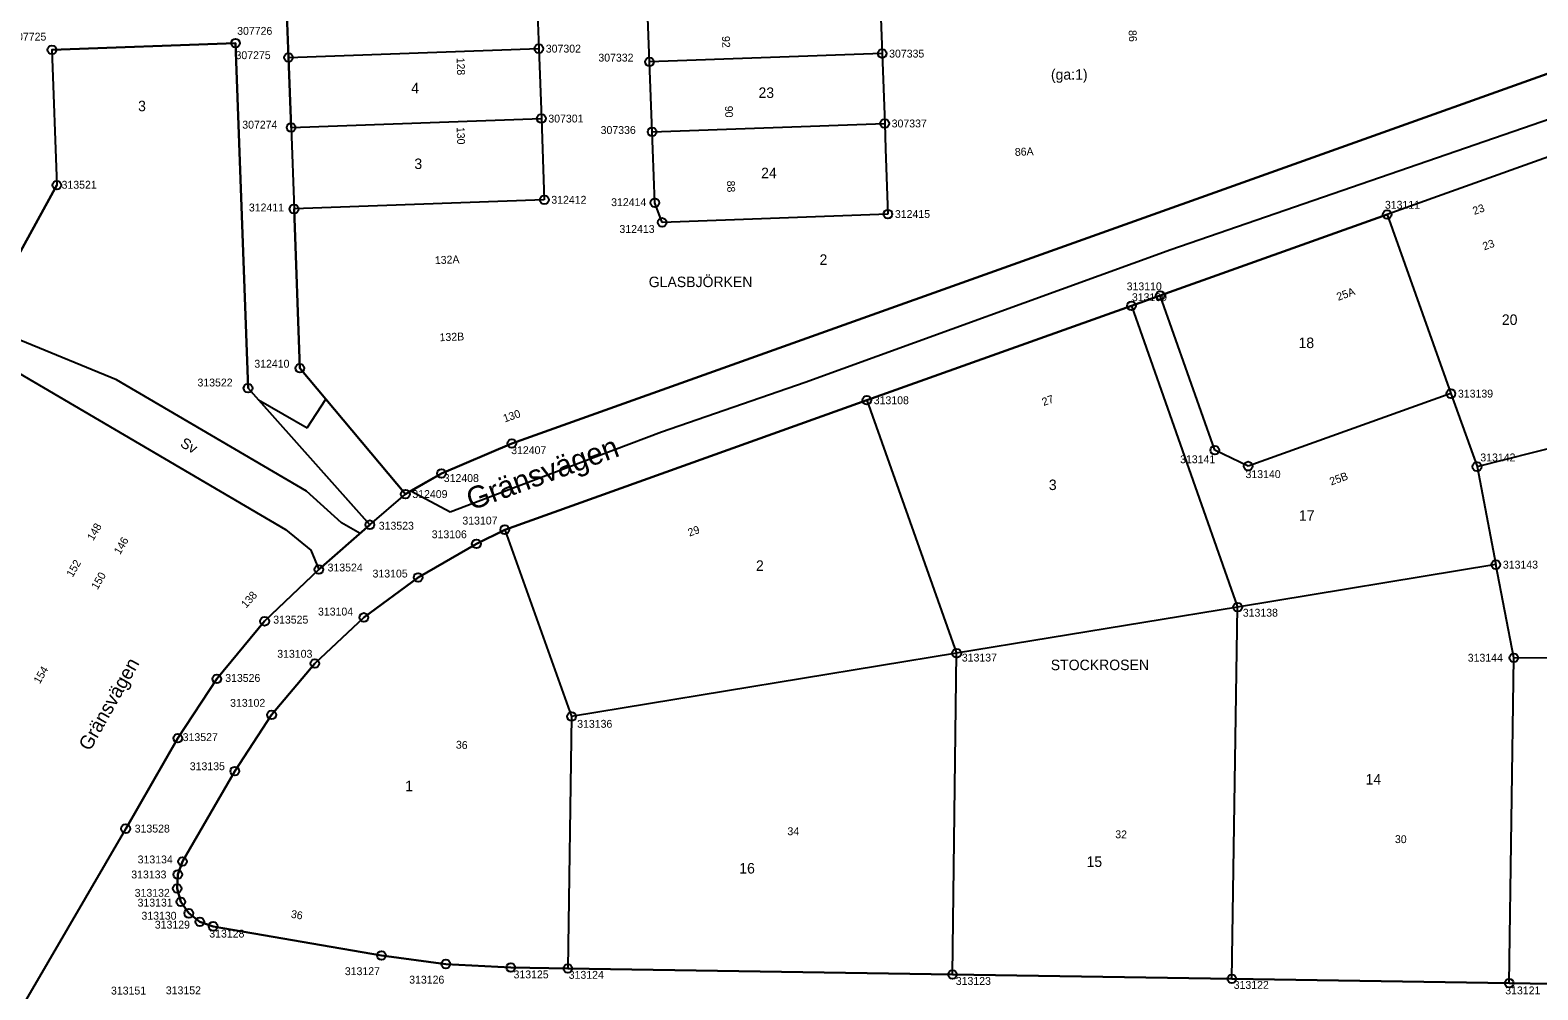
# Model space of a CAD drawing. Extents: x 141995 to 152570, y 6580184 to 6586000.
# Drawn here: x 142575.6 to 142748, y 6585148.7 to 6585258.5 of the extents above; entities that cross this region are included whole.
import ezdxf

# ---------------------------------------------------------------- set-up
doc = ezdxf.new("R2010")
doc.units = 0
for name, color, linetype in [('Level 10', 7, 'Continuous'), ('Level 13', 7, 'Continuous'), ('Level 33', 7, 'Continuous'), ('Level 41', 7, 'Continuous'), ('Level 43', 7, 'Continuous'), ('Level 48', 7, 'Continuous'), ('Level 5', 7, 'Continuous'), ('Level 50', 7, 'Continuous'), ('Level 51', 7, 'Continuous'), ('Level 53', 7, 'Continuous'), ('Level 54', 7, 'Continuous'), ('Level 55', 7, 'Continuous'), ('Level 58', 7, 'Continuous'), ('Level 59', 7, 'Continuous'), ('Level 6', 7, 'Continuous'), ('Level 7', 7, 'Continuous')]:
    doc.layers.add(name, color=color, linetype=linetype)

msp = doc.modelspace()

# ---------------------------------------------------------------- linework, layer by layer
at = {"layer": 'Level 10'}
for centre in [(142578.05, 6585256.21), (142599.03, 6585256.98), (142633.72, 6585256.34), (142605.1, 6585255.32), (142646.37, 6585254.82), (142672.98, 6585255.77), (142634.01, 6585248.34), (142673.27, 6585247.78), (142605.39, 6585247.32), (142646.67, 6585246.83), (142578.61, 6585240.72), (142634.35, 6585239.05), (142605.73, 6585238), (142646.98, 6585238.72), (142673.64, 6585237.42), (142730.72, 6585237.37), (142647.82, 6585236.47), (142701.48, 6585226.92), (142704.78, 6585228.1), (142606.4, 6585219.78), (142600.47, 6585217.5), (142738.02, 6585216.88), (142671.22, 6585216.12), (142630.63, 6585211.17), (142711.01, 6585210.42), (142622.58, 6585207.74), (142714.83, 6585208.6), (142741, 6585208.53), (142618.46, 6585205.39), (142614.41, 6585201.89), (142629.82, 6585201.32), (142626.58, 6585199.69), (142608.58, 6585196.76), (142619.91, 6585195.86), (142743.16, 6585197.32), (142713.63, 6585192.46), (142602.37, 6585190.84), (142613.72, 6585191.29), (142681.5, 6585187.18), (142608.11, 6585186.02), (142745.21, 6585186.67), (142596.9, 6585184.25), (142603.17, 6585180.13), (142637.47, 6585179.94), (142592.45, 6585177.46), (142598.95, 6585173.71), (142586.48, 6585167.12), (142592.98, 6585163.37), (142592.43, 6585161.88), (142592.36, 6585160.28), (142592.79, 6585158.75), (142593.69, 6585157.44), (142594.96, 6585156.47), (142596.47, 6585155.95), (142615.72, 6585152.61), (142623.08, 6585151.64), (142630.51, 6585151.24), (142637.03, 6585151.13), (142681.03, 6585150.44), (142712.96, 6585149.94), (142744.69, 6585149.45)]:
    msp.add_circle(centre, 0.5, dxfattribs=at)
at = {"layer": 'Level 13'}
msp.add_lwpolyline([(142614.41, 6585201.89), (142618.46, 6585205.39)], dxfattribs=at)
at = {"layer": 'Level 33'}
msp.add_lwpolyline([(142567.89, 6585221.24), (142555.96, 6585222.52), (142555.48, 6585218.05), (142560.06, 6585218.56), (142568.15, 6585217.7), (142574.22, 6585219.27), (142604.74, 6585201.34), (142607.64, 6585198.99), (142608.58, 6585196.76), (142613.29, 6585200.9), (142611.16, 6585202.1), (142607.15, 6585205.72), (142585.42, 6585218.45), (142574.48, 6585222.95)], close=True, dxfattribs=at)
at = {"layer": 'Level 5'}
for points in [[(142845.4, 6585287.91), (142630.63, 6585211.17)], [(142605.1, 6585255.32), (142604.8, 6585263.31)], [(142705.99, 6585233.38), (142788.63, 6585261.93)], [(142578.05, 6585256.21), (142599.03, 6585256.98)], [(142599.03, 6585256.98), (142600.47, 6585217.5)], [(142578.05, 6585256.21), (142578.61, 6585240.72)], [(142605.39, 6585247.32), (142605.1, 6585255.32)], [(142605.39, 6585247.32), (142605.73, 6585238)], [(142758.14, 6585247.18), (142730.72, 6585237.37)], [(142567.89, 6585221.24), (142578.61, 6585240.72)], [(142606.4, 6585219.78), (142605.73, 6585238)], [(142704.78, 6585228.1), (142730.72, 6585237.37)], [(142664.18, 6585218.18), (142705.99, 6585233.38)], [(142701.48, 6585226.92), (142704.78, 6585228.1)], [(142671.22, 6585216.12), (142701.48, 6585226.92)], [(142609.36, 6585216.24), (142606.4, 6585219.78)], [(142600.47, 6585217.5), (142601.65, 6585216.19)], [(142647.73, 6585212.5), (142664.18, 6585218.18)], [(142601.65, 6585216.19), (142614.41, 6585201.89)], [(142601.65, 6585216.19), (142607.24, 6585212.97)], [(142607.24, 6585212.97), (142609.36, 6585216.24)], [(142618.46, 6585205.39), (142609.36, 6585216.24)], [(142629.82, 6585201.32), (142671.22, 6585216.12)], [(142631.4, 6585206.32), (142647.73, 6585212.5)], [(142630.63, 6585211.17), (142622.58, 6585207.74)], [(142622.58, 6585207.74), (142619.1, 6585205.75)], [(142619.1, 6585205.75), (142618.46, 6585205.39)], [(142619.1, 6585205.75), (142623.59, 6585203.37)], [(142623.59, 6585203.37), (142631.4, 6585206.32)], [(142614.41, 6585201.89), (142608.58, 6585196.76)], [(142626.58, 6585199.69), (142629.82, 6585201.32)], [(142619.91, 6585195.86), (142626.58, 6585199.69)], [(142608.58, 6585196.76), (142602.37, 6585190.84)], [(142613.72, 6585191.29), (142619.91, 6585195.86)], [(142608.11, 6585186.02), (142613.72, 6585191.29)], [(142602.37, 6585190.84), (142596.9, 6585184.25)], [(142603.17, 6585180.13), (142608.11, 6585186.02)], [(142596.9, 6585184.25), (142592.45, 6585177.46)], [(142598.95, 6585173.71), (142603.17, 6585180.13)], [(142592.45, 6585177.46), (142586.48, 6585167.12)], [(142592.98, 6585163.37), (142598.95, 6585173.71)], [(142534.91, 6585078.61), (142586.48, 6585167.12)], [(142592.36, 6585160.28), (142592.43, 6585161.88)], [(142592.43, 6585161.88), (142592.98, 6585163.37)], [(142592.79, 6585158.75), (142592.36, 6585160.28)], [(142593.69, 6585157.44), (142592.79, 6585158.75)], [(142594.96, 6585156.47), (142593.69, 6585157.44)], [(142596.47, 6585155.95), (142594.96, 6585156.47)], [(142615.72, 6585152.61), (142596.47, 6585155.95)], [(142623.08, 6585151.64), (142615.72, 6585152.61)], [(142630.51, 6585151.24), (142623.08, 6585151.64)], [(142637.03, 6585151.13), (142630.51, 6585151.24)], [(142681.03, 6585150.44), (142637.03, 6585151.13)], [(142712.96, 6585149.94), (142681.03, 6585150.44)], [(142744.69, 6585149.45), (142712.96, 6585149.94)], [(142773.61, 6585149), (142744.69, 6585149.45)]]:
    msp.add_lwpolyline(points, dxfattribs=at)
at = {"layer": 'Level 6'}
for points in [[(142604.8, 6585263.31), (142605.1, 6585255.32), (142605.39, 6585247.32), (142605.73, 6585238), (142606.4, 6585219.78), (142618.46, 6585205.39), (142622.58, 6585207.74), (142630.63, 6585211.17), (142845.4, 6585287.91)], [(142534.91, 6585078.61), (142586.48, 6585167.12), (142592.45, 6585177.46), (142596.9, 6585184.25), (142602.37, 6585190.84), (142608.58, 6585196.76), (142614.41, 6585201.89), (142600.47, 6585217.5), (142599.03, 6585256.98), (142578.05, 6585256.21), (142578.61, 6585240.72), (142567.89, 6585221.24), (142555.96, 6585222.52), (142530.89, 6585225.21), (142526.9, 6585211.96), (142503.51, 6585213.49), (142466.9, 6585215.9), (142464.86, 6585179.94), (142457.88, 6585180.44), (142452.49, 6585105.64)], [(142758.14, 6585247.18), (142730.72, 6585237.37), (142704.78, 6585228.1), (142701.48, 6585226.92), (142671.22, 6585216.12), (142629.82, 6585201.32), (142626.58, 6585199.69), (142619.91, 6585195.86), (142613.72, 6585191.29), (142608.11, 6585186.02), (142603.17, 6585180.13), (142598.95, 6585173.71), (142592.98, 6585163.37), (142592.43, 6585161.88), (142592.36, 6585160.28), (142592.79, 6585158.75), (142593.69, 6585157.44), (142594.96, 6585156.47), (142596.47, 6585155.95), (142615.72, 6585152.61), (142623.08, 6585151.64), (142630.51, 6585151.24), (142637.03, 6585151.13), (142681.03, 6585150.44), (142712.96, 6585149.94), (142744.69, 6585149.45), (142773.61, 6585149)]]:
    msp.add_lwpolyline(points, dxfattribs=at)
at = {"layer": 'Level 7'}
for points in [[(142633.43, 6585264.33), (142633.72, 6585256.34)], [(142672.69, 6585263.85), (142672.98, 6585255.77)], [(142646.37, 6585254.82), (142646.06, 6585262.9)], [(142605.1, 6585255.32), (142633.72, 6585256.34)], [(142633.72, 6585256.34), (142634.01, 6585248.34)], [(142672.98, 6585255.77), (142646.37, 6585254.82)], [(142646.67, 6585246.83), (142646.37, 6585254.82)], [(142672.98, 6585255.77), (142673.27, 6585247.78)], [(142605.39, 6585247.32), (142634.01, 6585248.34)], [(142634.01, 6585248.34), (142634.35, 6585239.05)], [(142646.67, 6585246.83), (142673.27, 6585247.78)], [(142646.75, 6585244.81), (142646.67, 6585246.83)], [(142673.27, 6585247.78), (142673.37, 6585244.84)], [(142646.98, 6585238.72), (142646.75, 6585244.81)], [(142673.37, 6585244.84), (142673.64, 6585237.42)], [(142634.35, 6585239.05), (142605.73, 6585238)], [(142647.82, 6585236.47), (142646.98, 6585238.72)], [(142673.64, 6585237.42), (142647.82, 6585236.47)], [(142730.72, 6585237.37), (142738.02, 6585216.88)], [(142711.01, 6585210.42), (142704.78, 6585228.1)], [(142701.48, 6585226.92), (142713.63, 6585192.46)], [(142738.02, 6585216.88), (142714.83, 6585208.6)], [(142738.02, 6585216.88), (142741, 6585208.53)], [(142671.22, 6585216.12), (142681.5, 6585187.18)], [(142741, 6585208.53), (142760.29, 6585213.44)], [(142714.83, 6585208.6), (142711.01, 6585210.42)], [(142741, 6585208.53), (142743.16, 6585197.32)], [(142629.82, 6585201.32), (142637.47, 6585179.94)], [(142743.16, 6585197.32), (142713.63, 6585192.46)], [(142745.21, 6585186.67), (142743.16, 6585197.32)], [(142713.63, 6585192.46), (142681.5, 6585187.18)], [(142712.96, 6585149.94), (142713.63, 6585192.46)], [(142681.5, 6585187.18), (142637.47, 6585179.94)], [(142681.03, 6585150.44), (142681.5, 6585187.18)], [(142744.69, 6585149.45), (142745.21, 6585186.67)], [(142779.93, 6585186.43), (142745.21, 6585186.67)], [(142637.47, 6585179.94), (142637.03, 6585151.13)]]:
    msp.add_lwpolyline(points, dxfattribs=at)

# ---------------------------------------------------------------- texts
at = {"layer": 'Level 41'}
msp.add_text('Gränsvägen', height=2.5, rotation=20.2104, dxfattribs=at).set_placement((142626.01, 6585203.49))
at = {"layer": 'Level 43'}
msp.add_text('Gränsvägen', height=1.6, rotation=60.6965, dxfattribs=at).set_placement((142582.4, 6585175.91))
at = {"layer": 'Level 48'}
msp.add_text('Sv', height=1.2, rotation=329.5617, dxfattribs=at).set_placement((142592.62, 6585210.9))
at = {"layer": 'Level 50'}
msp.add_text('STOCKROSEN', height=1.2, rotation=0.0514, dxfattribs=at).set_placement((142692.26, 6585185.25))
at = {"layer": 'Level 51'}
for s, p in [('(ga:1)', (142692.28, 6585252.79)), ('4', (142619.13, 6585251.23)), ('23', (142658.84, 6585250.7)), ('3', (142619.49, 6585242.57)), ('24', (142659.14, 6585241.52)), ('20', (142743.84, 6585224.74)), ('18', (142720.59, 6585222.09)), ('3', (142692.04, 6585205.85)), ('17', (142720.64, 6585202.34)), ('2', (142658.55, 6585196.61)), ('1', (142618.43, 6585171.41)), ('14', (142728.26, 6585172.17)), ('15', (142696.35, 6585162.74)), ('16', (142656.64, 6585161.99))]:
    msp.add_text(s, height=1.2, rotation=0.0514, dxfattribs=at).set_placement(p)
at = {"layer": 'Level 53'}
for s, rotation, p in [('307726', 0.0514, (142599.23, 6585257.92)), ('307725', 0.0522, (142573.39, 6585257.26)), ('307302', 0.0514, (142634.52, 6585255.89)), ('307275', 0.0514, (142599.04, 6585255.14)), ('307332', 0.0514, (142640.53, 6585254.86)), ('307335', 0.0514, (142673.78, 6585255.32)), ('307274', 0.0514, (142599.81, 6585247.19)), ('307301', 0.0514, (142634.81, 6585247.89)), ('307337', 0.0514, (142674.07, 6585247.33)), ('307336', 0.0514, (142640.79, 6585246.58)), ('313521', 0.0522, (142579.15, 6585240.32)), ('312412', 0.0514, (142635.15, 6585238.6)), ('312414', 0.0514, (142641.99, 6585238.33)), ('312411', 0.0514, (142600.57, 6585237.72)), ('312415', 0.0514, (142674.44, 6585236.97)), ('313111', 0.0514, (142730.47, 6585238.03)), ('312413', 0.0514, (142642.94, 6585235.26)), ('313110', 0.0514, (142700.94, 6585228.7)), ('313109', 0.0514, (142701.54, 6585227.46)), ('312410', 0.0514, (142601.19, 6585219.85)), ('313522', 0.0514, (142594.69, 6585217.7)), ('313139', 0.0514, (142738.82, 6585216.43)), ('313108', 0.0514, (142672.02, 6585215.67)), ('312407', 0.0514, (142630.56, 6585209.96)), ('313142', 0.0514, (142741.38, 6585209.13)), ('313141', 0.0514, (142707.05, 6585208.92)), ('312408', 0.0514, (142622.85, 6585206.77)), ('313140', 0.0514, (142714.53, 6585207.22)), ('312409', 0.0514, (142619.26, 6585204.94)), ('313523', 0.0514, (142615.42, 6585201.32)), ('313107', 0.0514, (142624.98, 6585201.91)), ('313106', 0.0514, (142621.47, 6585200.34)), ('313524', 0.0514, (142609.57, 6585196.54)), ('313105', 0.0514, (142614.71, 6585195.85)), ('313143', 0.0514, (142743.96, 6585196.87)), ('313525', 0.0514, (142603.35, 6585190.58)), ('313104', 0.0514, (142608.47, 6585191.5)), ('313138', 0.0514, (142714.22, 6585191.37)), ('313103', 0.0514, (142603.81, 6585186.67)), ('313137', 0.0514, (142682.09, 6585186.24)), ('313144', 0.0514, (142739.94, 6585186.22)), ('313526', 0.0514, (142597.86, 6585183.91)), ('313102', 0.0514, (142598.42, 6585181.06)), ('313136', 0.0514, (142638.11, 6585178.66)), ('313527', 0.0514, (142593, 6585177.14)), ('313135', 0.0514, (142593.81, 6585173.81)), ('313528', 0.0514, (142587.51, 6585166.68)), ('313134', 0.0514, (142587.85, 6585163.15)), ('313133', 0.0514, (142587.12, 6585161.43)), ('313132', 0.0514, (142587.51, 6585159.33)), ('313131', 0.0514, (142587.84, 6585158.21)), ('313130', 0.0514, (142588.28, 6585156.71)), ('313129', 0.0514, (142589.81, 6585155.69)), ('313128', 0.0514, (142596.04, 6585154.67)), ('313127', 0.0514, (142611.54, 6585150.37)), ('313126', 0.0514, (142618.9, 6585149.4)), ('313125', 0.0514, (142630.83, 6585150)), ('313124', 0.0514, (142637.14, 6585149.95)), ('313123', 0.0514, (142681.4, 6585149.25)), ('313122', 0.0514, (142713.18, 6585148.8)), ('313151', 0.0514, (142584.8, 6585148.15)), ('313152', 0.0514, (142591.07, 6585148.18)), ('313121', 0.0514, (142744.23, 6585148.17))]:
    msp.add_text(s, height=0.9, rotation=rotation, dxfattribs=at).set_placement(p)
at = {"layer": 'Level 54'}
for s, rotation, p in [('86', 272.2469, (142701.16, 6585258.45)), ('92', 272.0679, (142654.66, 6585257.77)), ('128', 272.0899, (142624.32, 6585255.29)), ('90', 272.0679, (142655, 6585249.78)), ('130', 272.0899, (142624.32, 6585247.37)), ('86A', 2.2798, (142688.17, 6585244.07)), ('88', 272.0729, (142655.23, 6585241.23)), ('23', 19.5474, (142741.83, 6585233.26)), ('132A', 2.2421, (142621.85, 6585231.69)), ('25A', 19.6584, (142725.13, 6585227.49)), ('132B', 2.1976, (142622.39, 6585222.87)), ('27', 19.6534, (142691.44, 6585215.46)), ('25B', 20.0414, (142724.33, 6585206.37)), ('148', 59.7646, (142582.77, 6585199.99)), ('29', 19.6694, (142650.95, 6585200.52)), ('146', 59.7646, (142585.84, 6585198.4)), ('152', 59.7646, (142580.41, 6585195.81)), ('150', 59.7646, (142583.26, 6585194.39)), ('154', 59.7646, (142576.66, 6585183.62)), ('36', 356.8883, (142624.22, 6585176.29)), ('34', 359.1003, (142662.14, 6585166.38)), ('32', 359.1003, (142699.63, 6585166.03)), ('30', 359.1123, (142731.61, 6585165.48))]:
    msp.add_text(s, height=0.9, rotation=rotation, dxfattribs=at).set_placement(p)
at = {"layer": 'Level 55'}
for s, rotation, p in [('23', 19.5474, (142740.69, 6585237.31)), ('130', 19.0704, (142629.82, 6585213.58)), ('138', 48.2129, (142600.25, 6585192.28)), ('36', 350.1792, (142605.32, 6585156.95))]:
    msp.add_text(s, height=0.9, rotation=rotation, dxfattribs=at).set_placement(p)
at = {"layer": 'Level 58'}
msp.add_text('GLASBJÖRKEN', height=1.2, rotation=0.0514, dxfattribs=at).set_placement((142646.29, 6585229.06))
at = {"layer": 'Level 59'}
for s, p in [('3', (142587.9, 6585249.18)), ('2', (142665.82, 6585231.61))]:
    msp.add_text(s, height=1.2, rotation=0.0514, dxfattribs=at).set_placement(p)

doc.saveas('drawing.dxf')
